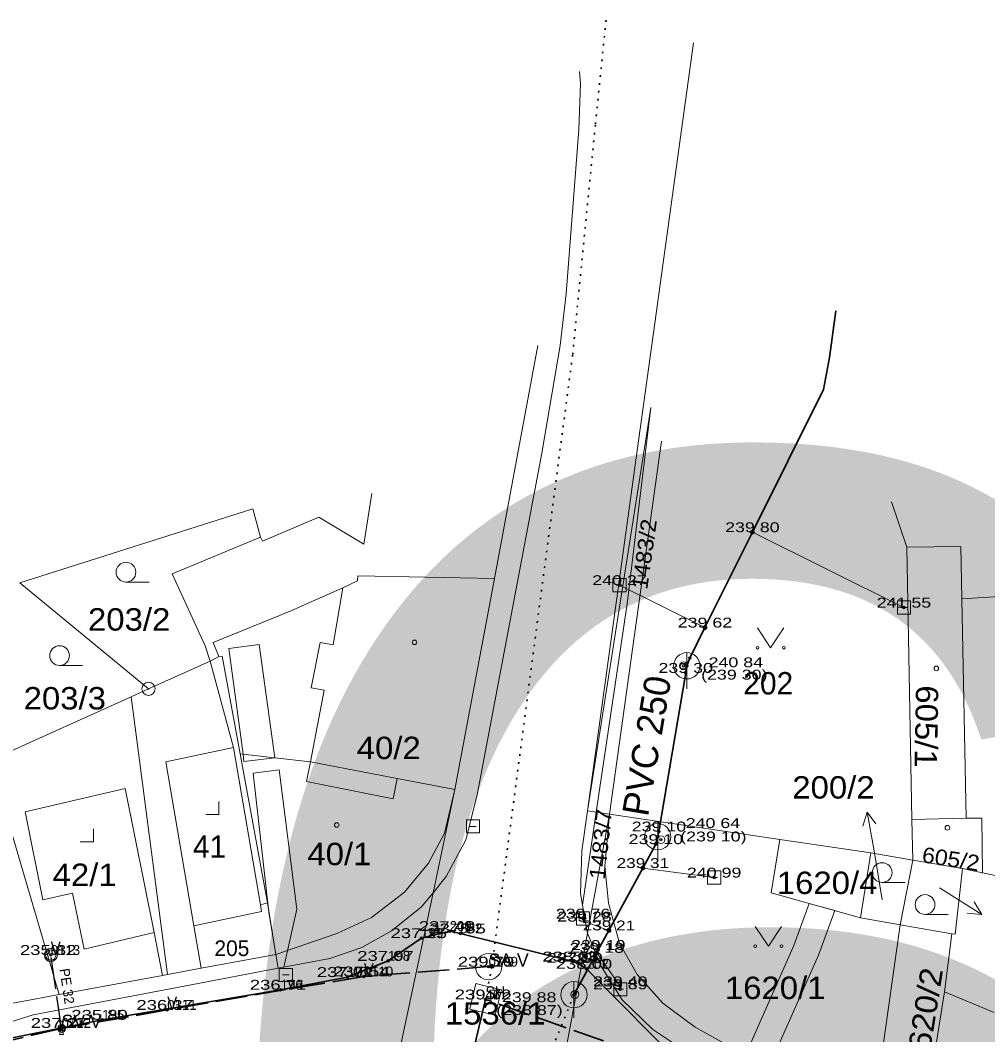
# Model space of a CAD drawing. Extents: x -686207 to -681951, y -1020493 to -1017811.
# Drawn here: x -682466.7 to -682393.2, y -1018853.5 to -1018776.4 of the extents above; entities that cross this region are included whole.
import ezdxf
from ezdxf.enums import TextEntityAlignment as Align

# ---------------------------------------------------------------- set-up
doc = ezdxf.new("R2010")
doc.units = 0
doc.header["$LTSCALE"] = 0.4
doc.header["$PDMODE"] = 32
doc.header["$PDSIZE"] = 0.2
doc.linetypes.add('DOTTED', pattern=[1.5, 0.3, -1.2])
doc.linetypes.add('LONG_DASHED', pattern=[7.5, 6, -1.5])
for name, color, linetype, lineweight in [('1', 7, 'Continuous', 13), ('10', 7, 'Continuous', 13), ('12', 7, 'Continuous', 13), ('13', 7, 'Continuous', 13), ('23', 7, 'Continuous', 13), ('3', 7, 'Continuous', 13), ('35', 7, 'LONG_DASHED', 35), ('36', 7, 'DOTTED', 35), ('4', 7, 'Continuous', 13), ('45', 7, 'Continuous', 35), ('46', 7, 'DOTTED', 35), ('5', 7, 'Continuous', 13), ('50', 7, 'LONG_DASHED', 25), ('7', 7, 'Continuous', 13), ('8', 7, 'Continuous', 13)]:
    doc.layers.add(name, color=color, linetype=linetype, lineweight=lineweight)
for name, color, linetype in [('15', 7, 'Continuous'), ('19', 7, 'Continuous'), ('2', 7, 'Continuous')]:
    doc.layers.add(name, color=color, linetype=linetype)

msp = doc.modelspace()

# ---------------------------------------------------------------- linework, layer by layer
at = {"layer": '1'}
for p, q in [((-682430.67, -1018818.85), (-682427.38, -1018801.14)), ((-682417.99, -1018808.41), (-682421.92, -1018836.75)), ((-682449.04, -1018813.56), (-682466.75, -1018819.18)), ((-682400.51, -1018813.02), (-682399.35, -1018816.48)), ((-682399.35, -1018816.48), (-682398.95, -1018837.15)), ((-682430.67, -1018818.85), (-682433.69, -1018834.88)), ((-682466.75, -1018819.18), (-682456.96, -1018827.23)), ((-682452.27, -1018825.12), (-682456.96, -1018827.23)), ((-682451.62, -1018824.77), (-682452.27, -1018825.12)), ((-682458.28, -1018827.83), (-682468.99, -1018832.67)), ((-682468.99, -1018832.67), (-682463.76, -1018850.46)), ((-682447.92, -1018843.49), (-682450, -1018832.17)), ((-682433.69, -1018834.88), (-682435.34, -1018842.72)), ((-682421.92, -1018836.75), (-682423.6, -1018845.79)), ((-682421.92, -1018836.75), (-682408.99, -1018838.67)), ((-682398.95, -1018837.15), (-682394.83, -1018837.07)), ((-682398.95, -1018837.15), (-682398.89, -1018840.24)), ((-682408.99, -1018838.67), (-682402.08, -1018839.69)), ((-682402.08, -1018839.69), (-682402.86, -1018844.62)), ((-682402.08, -1018839.69), (-682398.89, -1018840.24)), ((-682398.89, -1018840.24), (-682399.85, -1018845.15)), ((-682398.89, -1018840.24), (-682395.11, -1018840.88)), ((-682393.58, -1018841.21), (-682395.11, -1018840.88)), ((-682393.58, -1018841.21), (-682376.65, -1018844.81)), ((-682438.34, -1018856.91), (-682435.34, -1018842.72)), ((-682447.29, -1018847.42), (-682447.92, -1018843.49)), ((-682402.86, -1018844.62), (-682399.85, -1018845.15)), ((-682399.85, -1018845.15), (-682401.82, -1018859.17)), ((-682395.91, -1018845.84), (-682399.85, -1018845.15)), ((-682423.6, -1018845.79), (-682426.07, -1018859.13)), ((-682452.96, -1018848.46), (-682447.29, -1018847.42)), ((-682455.52, -1018848.94), (-682452.96, -1018848.46))]:
    msp.add_line(p, q, dxfattribs=at)
for points in [[(-682423.61, -1018836.5), (-682419.59, -1018807.47), (-682418.7, -1018800.91), (-682415.55, -1018778.16)], [(-682435.34, -1018842.72), (-682434.34, -1018841.49), (-682432.85, -1018838.71), (-682431.98, -1018835.28), (-682427.07, -1018809.32), (-682425.67, -1018801.15), (-682425.23, -1018797.22), (-682424.26, -1018784.75), (-682424.14, -1018781.27), (-682424.2, -1018780.34)], [(-682418.78, -1018805.85), (-682423.61, -1018836.5), (-682421.92, -1018836.75)], [(-682449.04, -1018813.56), (-682448.44, -1018815.72), (-682455.17, -1018818.49), (-682452.66, -1018823.96), (-682452.27, -1018825.12)], [(-682399.35, -1018816.48), (-682395.24, -1018816.42), (-682395.16, -1018820.39), (-682394.83, -1018837.07)], [(-682451.62, -1018824.77), (-682452.04, -1018823.71), (-682446.21, -1018821.34), (-682442.19, -1018819.55), (-682441.07, -1018819.03), (-682441.06, -1018818.66), (-682430.67, -1018818.85)], [(-682450, -1018832.17), (-682451.36, -1018824.74), (-682451.62, -1018824.77)], [(-682456.96, -1018827.23), (-682458.28, -1018827.83), (-682455.52, -1018848.94)], [(-682433.69, -1018834.88), (-682438.06, -1018834.05), (-682444.66, -1018832.79), (-682447.37, -1018832.48), (-682449.78, -1018832.2), (-682450, -1018832.17)], [(-682423.6, -1018845.79), (-682423.64, -1018845.69), (-682424.13, -1018842.77), (-682424.03, -1018839.54), (-682423.61, -1018836.5)], [(-682401.82, -1018859.17), (-682412.5, -1018854.56), (-682415.42, -1018852.93), (-682417.87, -1018851.11), (-682419.84, -1018848.93), (-682421.17, -1018846.55), (-682422.02, -1018843.51), (-682422.29, -1018840.71), (-682421.92, -1018836.75)], [(-682394.83, -1018837.07), (-682393.63, -1018837.05), (-682393.58, -1018841.21)], [(-682402.86, -1018844.62), (-682409.64, -1018842.74), (-682408.99, -1018838.67)], [(-682395.11, -1018840.88), (-682395.67, -1018845.88), (-682395.91, -1018845.84)], [(-682435.34, -1018842.72), (-682436.25, -1018843.82), (-682438.5, -1018845.63), (-682440.75, -1018846.89), (-682443.19, -1018847.72), (-682447.12, -1018848.46), (-682447.29, -1018847.42)], [(-682452.96, -1018848.46), (-682453.51, -1018845.23), (-682448.37, -1018844.15), (-682448.46, -1018843.64), (-682447.92, -1018843.49)], [(-682423.6, -1018845.79), (-682422.59, -1018848.27), (-682420.98, -1018850.85), (-682418.65, -1018853.11), (-682415.98, -1018854.89), (-682379.32, -1018870.75), (-682363.52, -1018878.15), (-682349.05, -1018885.65), (-682332.94, -1018900.32), (-682313.79, -1018921.05), (-682313.26, -1018921.31), (-682312.65, -1018921.28), (-682311.66, -1018920.35)], [(-682395.91, -1018845.84), (-682396.47, -1018850.25), (-682398.15, -1018860.76)], [(-682463.76, -1018850.46), (-682455.89, -1018849), (-682455.52, -1018848.94)], [(-682472.32, -1018851.99), (-682466.71, -1018851.02), (-682463.76, -1018850.46)]]:
    msp.add_lwpolyline(points, dxfattribs=at)
for p in [(-682411.076, -1018815.33), (-682421.17, -1018819.353), (-682399.556, -1018821.059), (-682414.68, -1018822.576), (-682415.831, -1018824.891), (-682416.307, -1018825.487), (-682416.143, -1018826.019), (-682416.058, -1018825.482), (-682418.176, -1018838.068), (-682418.412, -1018839.029), (-682418.266, -1018838.466), (-682418.024, -1018838.693), (-682419.4, -1018840.847), (-682413.98, -1018841.571), (-682423.942, -1018844.687), (-682423.832, -1018844.912), (-682434.081, -1018845.636), (-682433.281, -1018845.816), (-682421.976, -1018845.585), (-682436.23, -1018846.171), (-682464.39, -1018847.45), (-682422.9, -1018847.287), (-682422.783, -1018847.071), (-682438.761, -1018847.898), (-682431.12, -1018848.34), (-682424.692, -1018847.948), (-682424.383, -1018848.049), (-682441.83, -1018849.128), (-682440.6, -1018849.08), (-682423.678, -1018848.505), (-682421.112, -1018849.834), (-682446.92, -1018850.092), (-682424.633, -1018850.473), (-682424.56, -1018850.452), (-682421.111, -1018850.058), (-682431.35, -1018850.83), (-682455.54, -1018851.62), (-682463.57, -1018852.99), (-682460.488, -1018852.375)]:
    msp.add_point(p, dxfattribs=at)
at = {"layer": '10'}
for p, q in [((-682420.92, -1018819.353), (-682421.42, -1018819.353)), ((-682399.306, -1018821.059), (-682399.806, -1018821.059)), ((-682416.058, -1018824.482), (-682416.058, -1018827.23)), ((-682418.266, -1018837.466), (-682418.266, -1018840.214)), ((-682432.06, -1018837.68), (-682432.56, -1018837.68)), ((-682413.73, -1018841.571), (-682414.23, -1018841.571)), ((-682423.692, -1018844.687), (-682424.192, -1018844.687)), ((-682446.28, -1018848.97), (-682446.78, -1018848.97)), ((-682424.633, -1018849.473), (-682424.633, -1018852.221)), ((-682420.861, -1018850.058), (-682421.361, -1018850.058))]:
    msp.add_line(p, q, dxfattribs=at)
for points in [[(-682420.67, -1018818.853), (-682421.67, -1018818.853), (-682421.67, -1018819.853), (-682420.67, -1018819.853)], [(-682399.056, -1018820.559), (-682400.056, -1018820.559), (-682400.056, -1018821.559), (-682399.056, -1018821.559)], [(-682431.81, -1018837.18), (-682432.81, -1018837.18), (-682432.81, -1018838.18), (-682431.81, -1018838.18)], [(-682413.48, -1018841.071), (-682414.48, -1018841.071), (-682414.48, -1018842.071), (-682413.48, -1018842.071)], [(-682423.442, -1018844.187), (-682424.442, -1018844.187), (-682424.442, -1018845.187), (-682423.442, -1018845.187)], [(-682446.03, -1018848.47), (-682447.03, -1018848.47), (-682447.03, -1018849.47), (-682446.03, -1018849.47)], [(-682430.144, -1018850.092), (-682430.612, -1018852.036), (-682432.556, -1018851.568), (-682432.088, -1018849.624)], [(-682420.611, -1018849.558), (-682421.611, -1018849.558), (-682421.611, -1018850.558), (-682420.611, -1018850.558)], [(-682463.42, -1018853.49), (-682463.72, -1018852.49), (-682463.42, -1018852.49), (-682463.72, -1018853.49)]]:
    msp.add_lwpolyline(points, close=True, dxfattribs=at)
for centre, radius in [((-682416.058, -1018825.483), 1.0002), ((-682418.266, -1018838.467), 1.0002), ((-682431.12, -1018848.34), 1), ((-682424.633, -1018850.474), 1.0002)]:
    msp.add_circle(centre, radius, dxfattribs=at)
at = {"layer": '12'}
for centre, radius in [((-682411.076, -1018815.33), 0.15), ((-682411.076, -1018815.33), 0.075), ((-682414.68, -1018822.576), 0.15), ((-682414.68, -1018822.576), 0.075), ((-682419.4, -1018840.846), 0.15), ((-682419.4, -1018840.846), 0.075), ((-682421.976, -1018845.585), 0.15), ((-682421.976, -1018845.585), 0.075), ((-682464.39, -1018847.45), 0.5), ((-682464.39, -1018847.45), 0.4), ((-682422.9, -1018847.287), 0.15), ((-682422.9, -1018847.287), 0.075), ((-682430.871, -1018848.321), 0.15), ((-682430.871, -1018848.321), 0.075), ((-682463.563, -1018853.039), 0.3), ((-682463.563, -1018853.039), 0.2), ((-682463.563, -1018853.039), 0.1)]:
    msp.add_circle(centre, radius, dxfattribs=at)
at = {"layer": '13'}
for points in [[(-682420.6, -1018820.78), (-682418.78, -1018805.85), (-682423.61, -1018836.5), (-682424.03, -1018839.54), (-682424.13, -1018842.77), (-682423.98, -1018843.66), (-682422.94, -1018836.6)], [(-682446.69, -1018848.38), (-682445.69, -1018843.97), (-682447.03, -1018833.39), (-682449.01, -1018833.65), (-682447.81, -1018844.19), (-682447.29, -1018847.42), (-682447.12, -1018848.46)], [(-682406.06, -1018847.46), (-682404.82, -1018844.08), (-682406.75, -1018843.54), (-682407.92, -1018846.72), (-682411.17, -1018854.07), (-682411.63, -1018854.94), (-682412.42, -1018856.43), (-682410.58, -1018857.23), (-682409.78, -1018855.73), (-682409.37, -1018854.95)]]:
    msp.add_lwpolyline(points, close=True, dxfattribs=at)
for centre in [(-682416.307, -1018825.487), (-682418.024, -1018838.693), (-682424.56, -1018850.452)]:
    msp.add_circle(centre, 0.3, dxfattribs=at)
at = {"layer": '23'}
msp.add_line((-682424.692, -1018847.948), (-682433.281, -1018845.816), dxfattribs=at)
at = {"layer": '3'}
for p, q in [((-682458.673, -1018819.12), (-682456.923, -1018819.12)), ((-682463.723, -1018825.46), (-682461.973, -1018825.46)), ((-682401.213, -1018841.94), (-682399.463, -1018841.94)), ((-682397.953, -1018844.37), (-682396.203, -1018844.37))]:
    msp.add_line(p, q, dxfattribs=at)
for points in [[(-682410.69, -1018822.609), (-682409.69, -1018824.11), (-682408.69, -1018822.609)], [(-682452.611, -1018836.78), (-682451.61, -1018836.78), (-682451.61, -1018835.78)], [(-682462.151, -1018838.86), (-682461.15, -1018838.86), (-682461.15, -1018837.86)], [(-682410.86, -1018845.289), (-682409.86, -1018846.79), (-682408.86, -1018845.289)]]:
    msp.add_lwpolyline(points, dxfattribs=at)
for centre, radius in [((-682458.6729, -1018818.3698), 0.75), ((-682463.7229, -1018824.7098), 0.75), ((-682410.69, -1018824.1095), 0.1), ((-682408.69, -1018824.1095), 0.1), ((-682401.2129, -1018841.1898), 0.75), ((-682397.9529, -1018843.6198), 0.75), ((-682410.86, -1018846.7895), 0.1), ((-682408.86, -1018846.7895), 0.1)]:
    msp.add_circle(centre, radius, dxfattribs=at)
at = {"layer": '35'}
for p, q in [((-682430.871, -1018848.321), (-682431.12, -1018848.34)), ((-682411.062, -1018857.953), (-682431.35, -1018850.83)), ((-682463.563, -1018853.039), (-682473.785, -1018855.382))]:
    msp.add_line(p, q, dxfattribs=at)
at = {"layer": '35', "linetype": 'Continuous'}
msp.add_line((-682431.35, -1018850.83), (-682432.82, -1018856.93), dxfattribs=at)
at = {"layer": '35'}
msp.add_lwpolyline([(-682431.12, -1018848.34), (-682440.6, -1018849.08), (-682455.54, -1018851.62), (-682463.563, -1018853.039)], dxfattribs=at)
at = {"layer": '36'}
msp.add_lwpolyline([(-682422.195, -1018776.441), (-682423.008, -1018784.39), (-682424.735, -1018801.872), (-682430.871, -1018848.321), (-682431.35, -1018850.83)], dxfattribs=at)
at = {"layer": '4'}
for p, q in [((-682440.61, -1018816.24), (-682440, -1018812.4)), ((-682448.31, -1018816.02), (-682444.01, -1018814.2)), ((-682444.01, -1018814.2), (-682440.61, -1018816.24)), ((-682448.44, -1018815.72), (-682448.31, -1018816.02)), ((-682442.93, -1018823.88), (-682442.19, -1018819.55)), ((-682395.16, -1018820.39), (-682383.11, -1018819.69)), ((-682450.86, -1018824.17), (-682449.78, -1018832.2)), ((-682444.6, -1018827.15), (-682443.93, -1018823.71)), ((-682443.93, -1018823.71), (-682442.93, -1018823.88)), ((-682452.27, -1018825.12), (-682450.51, -1018831.68)), ((-682444.6, -1018827.15), (-682443.62, -1018827.34)), ((-682455.64, -1018832.77), (-682450.51, -1018831.68)), ((-682450.51, -1018831.68), (-682448.46, -1018843.64)), ((-682455.64, -1018832.77), (-682453.51, -1018845.23)), ((-682449.78, -1018832.2), (-682449.71, -1018832.75)), ((-682449.71, -1018832.75), (-682447.37, -1018832.48)), ((-682444.95, -1018834.28), (-682438.36, -1018835.58)), ((-682438.36, -1018835.58), (-682438.06, -1018834.05)), ((-682466.34, -1018836.58), (-682458.73, -1018834.81)), ((-682458.73, -1018834.81), (-682456.54, -1018845.74)), ((-682440.02, -1018844.6), (-682437.52, -1018842.67)), ((-682461.84, -1018847), (-682456.54, -1018845.74)), ((-682456.54, -1018845.74), (-682455.89, -1018849)), ((-682453.71, -1018849.71), (-682447.12, -1018848.46)), ((-682465.73, -1018851.99), (-682453.71, -1018849.71)), ((-682396.47, -1018850.25), (-682392.69, -1018851.83)), ((-682478.44, -1018856), (-682465.73, -1018851.99))]:
    msp.add_line(p, q, dxfattribs=at)
for points in [[(-682450.86, -1018824.17), (-682448.55, -1018823.86), (-682447.37, -1018832.48)], [(-682444.95, -1018834.28), (-682444.66, -1018832.79), (-682443.62, -1018827.34)], [(-682437.52, -1018842.67), (-682435.68, -1018840.47), (-682434.48, -1018838.19), (-682433.69, -1018834.88)], [(-682466.34, -1018836.58), (-682464.98, -1018843.26), (-682462.74, -1018842.76), (-682461.84, -1018847)], [(-682447.29, -1018847.42), (-682442.64, -1018845.81), (-682440.02, -1018844.6)]]:
    msp.add_lwpolyline(points, dxfattribs=at)
at = {"layer": '45'}
msp.add_line((-682422.9, -1018847.287), (-682424.633, -1018850.473), dxfattribs=at)
for points in [[(-682404.724, -1018798.502), (-682405.204, -1018802.056), (-682405.682, -1018804.483), (-682411.076, -1018815.33), (-682414.68, -1018822.576)], [(-682414.68, -1018822.576), (-682415.831, -1018824.891), (-682416.058, -1018825.482)], [(-682416.058, -1018825.482), (-682416.143, -1018826.019), (-682418.176, -1018838.068), (-682418.266, -1018838.466)], [(-682418.266, -1018838.466), (-682418.412, -1018839.029), (-682419.4, -1018840.846), (-682421.976, -1018845.585)], [(-682531.082, -1018881.094), (-682518.33, -1018875.007), (-682504.44, -1018867.923), (-682492.949, -1018862.559), (-682481.895, -1018857.673), (-682472.651, -1018854.808), (-682460.488, -1018852.375), (-682446.92, -1018850.092), (-682441.83, -1018849.128), (-682438.761, -1018847.898), (-682436.23, -1018846.171), (-682434.081, -1018845.636), (-682433.281, -1018845.816), (-682424.692, -1018847.948), (-682424.383, -1018848.049), (-682423.678, -1018848.505), (-682416.162, -1018856.096), (-682414.626, -1018857.087), (-682399.52, -1018863.943), (-682384.234, -1018870.749)], [(-682421.976, -1018845.585), (-682422.783, -1018847.071), (-682422.9, -1018847.287)]]:
    msp.add_lwpolyline(points, dxfattribs=at)
at = {"layer": '46'}
msp.add_line((-682424.633, -1018850.473), (-682427.576, -1018857.745), dxfattribs=at)
at = {"layer": '5'}
for centre in [(-682436.7468, -1018823.6992), (-682397.0968, -1018825.6792), (-682442.6568, -1018837.5792), (-682396.2568, -1018837.7892)]:
    msp.add_circle(centre, 0.175, dxfattribs=at)
at = {"layer": '50', "linetype": 'Continuous', "lineweight": 13}
for p, q in [((-682399.556, -1018821.059), (-682411.076, -1018815.33)), ((-682421.17, -1018819.353), (-682414.68, -1018822.576)), ((-682413.98, -1018841.571), (-682419.4, -1018840.846))]:
    msp.add_line(p, q, dxfattribs=at)
for points in [[(-682423.942, -1018844.687), (-682423.832, -1018844.912), (-682421.976, -1018845.585)], [(-682421.111, -1018850.058), (-682421.112, -1018849.834), (-682422.9, -1018847.287)]]:
    msp.add_lwpolyline(points, dxfattribs=at)
at = {"layer": '50'}
msp.add_lwpolyline([(-682463.563, -1018853.039), (-682463.57, -1018852.99), (-682464.39, -1018847.45)], dxfattribs=at)
at = {"layer": '7'}
for p, q in [((-682402.351, -1018836.595), (-682402.67, -1018837.668)), ((-682396.86, -1018842.36), (-682396.18, -1018842.79)), ((-682393.635, -1018844.38), (-682394.219, -1018843.425))]:
    msp.add_line(p, q, dxfattribs=at)
for points in [[(-682401.2, -1018843.27), (-682401.83, -1018839.55), (-682402.351, -1018836.595), (-682401.684, -1018837.494)], [(-682396.18, -1018842.79), (-682393.635, -1018844.38), (-682394.75, -1018844.274)]]:
    msp.add_lwpolyline(points, dxfattribs=at)
at = {"layer": '8'}
for radius in [0.5, 0.0303]:
    msp.add_circle((-682456.96, -1018827.2299), radius, dxfattribs=at)

# ---------------------------------------------------------------- texts
at = {"layer": '15'}
msp.add_text('PVC 250', height=2, rotation=80.423, dxfattribs=at).set_placement((-682418.1185, -1018831.7219), align=Align.CENTER)
at = {"layer": '19'}
msp.add_text('PE 32', height=0.75, rotation=278.419, dxfattribs=at).set_placement((-682463.5251, -1018849.8801), align=Align.CENTER)
at = {"layer": '2', "width": 1.1}
for s, height, rotation, p in [('1483/2', 1.19, 82, (-682419.07, -1018819.732)), ('605/1', 1.7, 269, (-682398.641, -1018826.952)), ('1483/7', 1.19, 84, (-682422.298, -1018841.762)), ('605/2', 1.19, 351, (-682398.25, -1018840.403)), ('1620/2', 1.7, 81, (-682397.777, -1018856.138))]:
    msp.add_text(s, height=height, rotation=rotation, dxfattribs=at).set_placement(p)
for s, p in [('203/2', (-682461.563, -1018822.809)), ('203/3', (-682466.453, -1018828.799)), ('40/2', (-682441.14, -1018832.57)), ('200/2', (-682408.043, -1018835.57)), ('40/1', (-682444.89, -1018840.63)), ('42/1', (-682464.25, -1018842.21)), ('1620/4', (-682409.22, -1018842.82)), ('1620/1', (-682413.165, -1018850.799)), ('1536/1', (-682434.445, -1018852.74))]:
    msp.add_text(s, height=1.7, dxfattribs=at).set_placement(p)
at = {"layer": '2'}
for s, height, p in [('202', 1.7, (-682411.764, -1018827.66)), ('41', 1.7, (-682453.592, -1018840.07)), ('200', 0.75, (-682434.08, -1018845.63)), ('582', 0.75, (-682433.28, -1018845.81)), ('199', 0.75, (-682436.23, -1018846.17)), ('0113', 0.75, (-682464.39, -1018847.45)), ('205', 1.19, (-682451.952, -1018847.534)), ('198', 0.75, (-682438.76, -1018847.89)), ('583', 0.75, (-682424.69, -1018847.94)), ('201', 0.75, (-682424.38, -1018848.04)), ('0110', 0.75, (-682440.6, -1018849.08)), ('0109', 0.75, (-682431.12, -1018848.34)), ('202', 0.75, (-682423.67, -1018848.5)), ('197', 0.75, (-682441.83, -1018849.12)), ('196', 0.75, (-682446.92, -1018850.09)), ('46', 0.75, (-682431.35, -1018850.83)), ('0111', 0.75, (-682455.54, -1018851.62)), ('195', 0.75, (-682460.48, -1018852.37)), ('0112', 0.75, (-682463.57, -1018852.99))]:
    msp.add_text(s, height=height, dxfattribs=at).set_placement(p)
at = {"layer": '23', "width": 1.15}
msp.add_text('681679', height=100, dxfattribs=at).set_placement((-682200.0295, -1018910), align=Align.CENTER)
at = {"layer": '3'}
for s, width, p in [('239 80', 1.35, (-682411.0755, -1018815.33)), ('240 27', 1.35, (-682421.1695, -1018819.353)), ('241 55', 1.35, (-682399.5555, -1018821.059)), ('239 62', 1.35, (-682414.6795, -1018822.576)), ('240 84', 1.35, (-682412.3315, -1018825.592)), ('239 30', 1.35, (-682416.1425, -1018826.019)), ('(239 30)', 1.35, (-682412.4485, -1018826.529)), ('239 10', 1.35, (-682418.1755, -1018838.068)), ('240 64', 1.35, (-682414.0715, -1018837.809)), ('239 10', 1.35, (-682418.4115, -1018839.029)), ('(239 10)', 1.35, (-682414.0395, -1018838.826)), ('239 31', 1.3, (-682419.3995, -1018840.846)), ('240 99', 1.35, (-682413.9795, -1018841.571)), ('239 76', 1.35, (-682423.9415, -1018844.687)), ('239 28', 1.35, (-682423.8315, -1018844.912)), ('237 49 ', 1.4, (-682434.081, -1018845.636)), ('237 55 ', 1.4, (-682433.281, -1018845.816)), ('239 21', 1.3, (-682421.9755, -1018845.585)), ('237 25 ', 1.4, (-682436.23, -1018846.171)), ('235 82 ', 1.4, (-682464.39, -1018847.45)), ('239 18', 1.35, (-682422.8995, -1018847.287)), ('239 19', 1.35, (-682422.7825, -1018847.071)), ('237 07 ', 1.4, (-682438.761, -1018847.898)), ('238 03 ', 1.4, (-682424.692, -1018847.948)), ('237 99 ', 1.4, (-682424.383, -1018848.049)), ('237 54 ', 1.4, (-682440.6, -1018849.08)), ('239 79 ', 1.4, (-682431.12, -1018848.34)), ('238 00 ', 1.4, (-682423.678, -1018848.505)), ('237 02 ', 1.4, (-682441.83, -1018849.128)), ('239 40', 1.35, (-682421.1115, -1018849.834)), ('236 71 ', 1.4, (-682446.92, -1018850.092)), ('239 89', 1.35, (-682421.1105, -1018850.058)), ('239 72 ', 1.4, (-682431.35, -1018850.83)), ('239 88', 1.35, (-682428.0365, -1018851.035)), ('236 37 ', 1.4, (-682455.54, -1018851.62)), ('(238 87)', 1.35, (-682428.0135, -1018852.015)), ('235 80 ', 1.4, (-682460.488, -1018852.375)), ('237 27 ', 1.4, (-682463.57, -1018852.99))]:
    msp.add_text(s, height=0.75, dxfattribs=dict(at, width=width)).set_placement(p, align=Align.CENTER)
at = {"layer": '4'}
for s, width, p in [('V', 0.85, (-682464.39, -1018847.45)), ('V', 0.85, (-682440.6, -1018849.08)), ('SH', 0.8, (-682431.35, -1018850.83)), ('V', 0.85, (-682455.54, -1018851.62))]:
    msp.add_text(s, height=1, dxfattribs=dict(at, width=width)).set_placement(p)
for s, p in [('SA V', (-682431.12, -1018848.34)), ('SV V', (-682463.57, -1018852.99))]:
    msp.add_text(s, height=1, dxfattribs=at).set_placement(p)

doc.saveas('drawing.dxf')
